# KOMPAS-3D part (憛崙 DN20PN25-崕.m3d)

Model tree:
1. Объединить компоненты:1

Referenced files in D:\Савин\!СЕНСОР\3D для заказчика\СЕНС\СЕНС DN15PN25-НО\Сборка\: Клапан DN20.a3d
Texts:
  СЕНС DN20PN25-НО
  ООО НПП Сенсор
